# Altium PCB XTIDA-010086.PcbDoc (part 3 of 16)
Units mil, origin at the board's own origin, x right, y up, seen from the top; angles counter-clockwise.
Board outline 14763.78 x 8267.72 mil, 6 copper layers (Top Layer, GND Layer, Signal Layer 1, Signal Layer 2, Power Layer, Bottom Layer), stack 62 mil thick; 1933 components, 1002 nets, 4886 pads, 6482 vias.
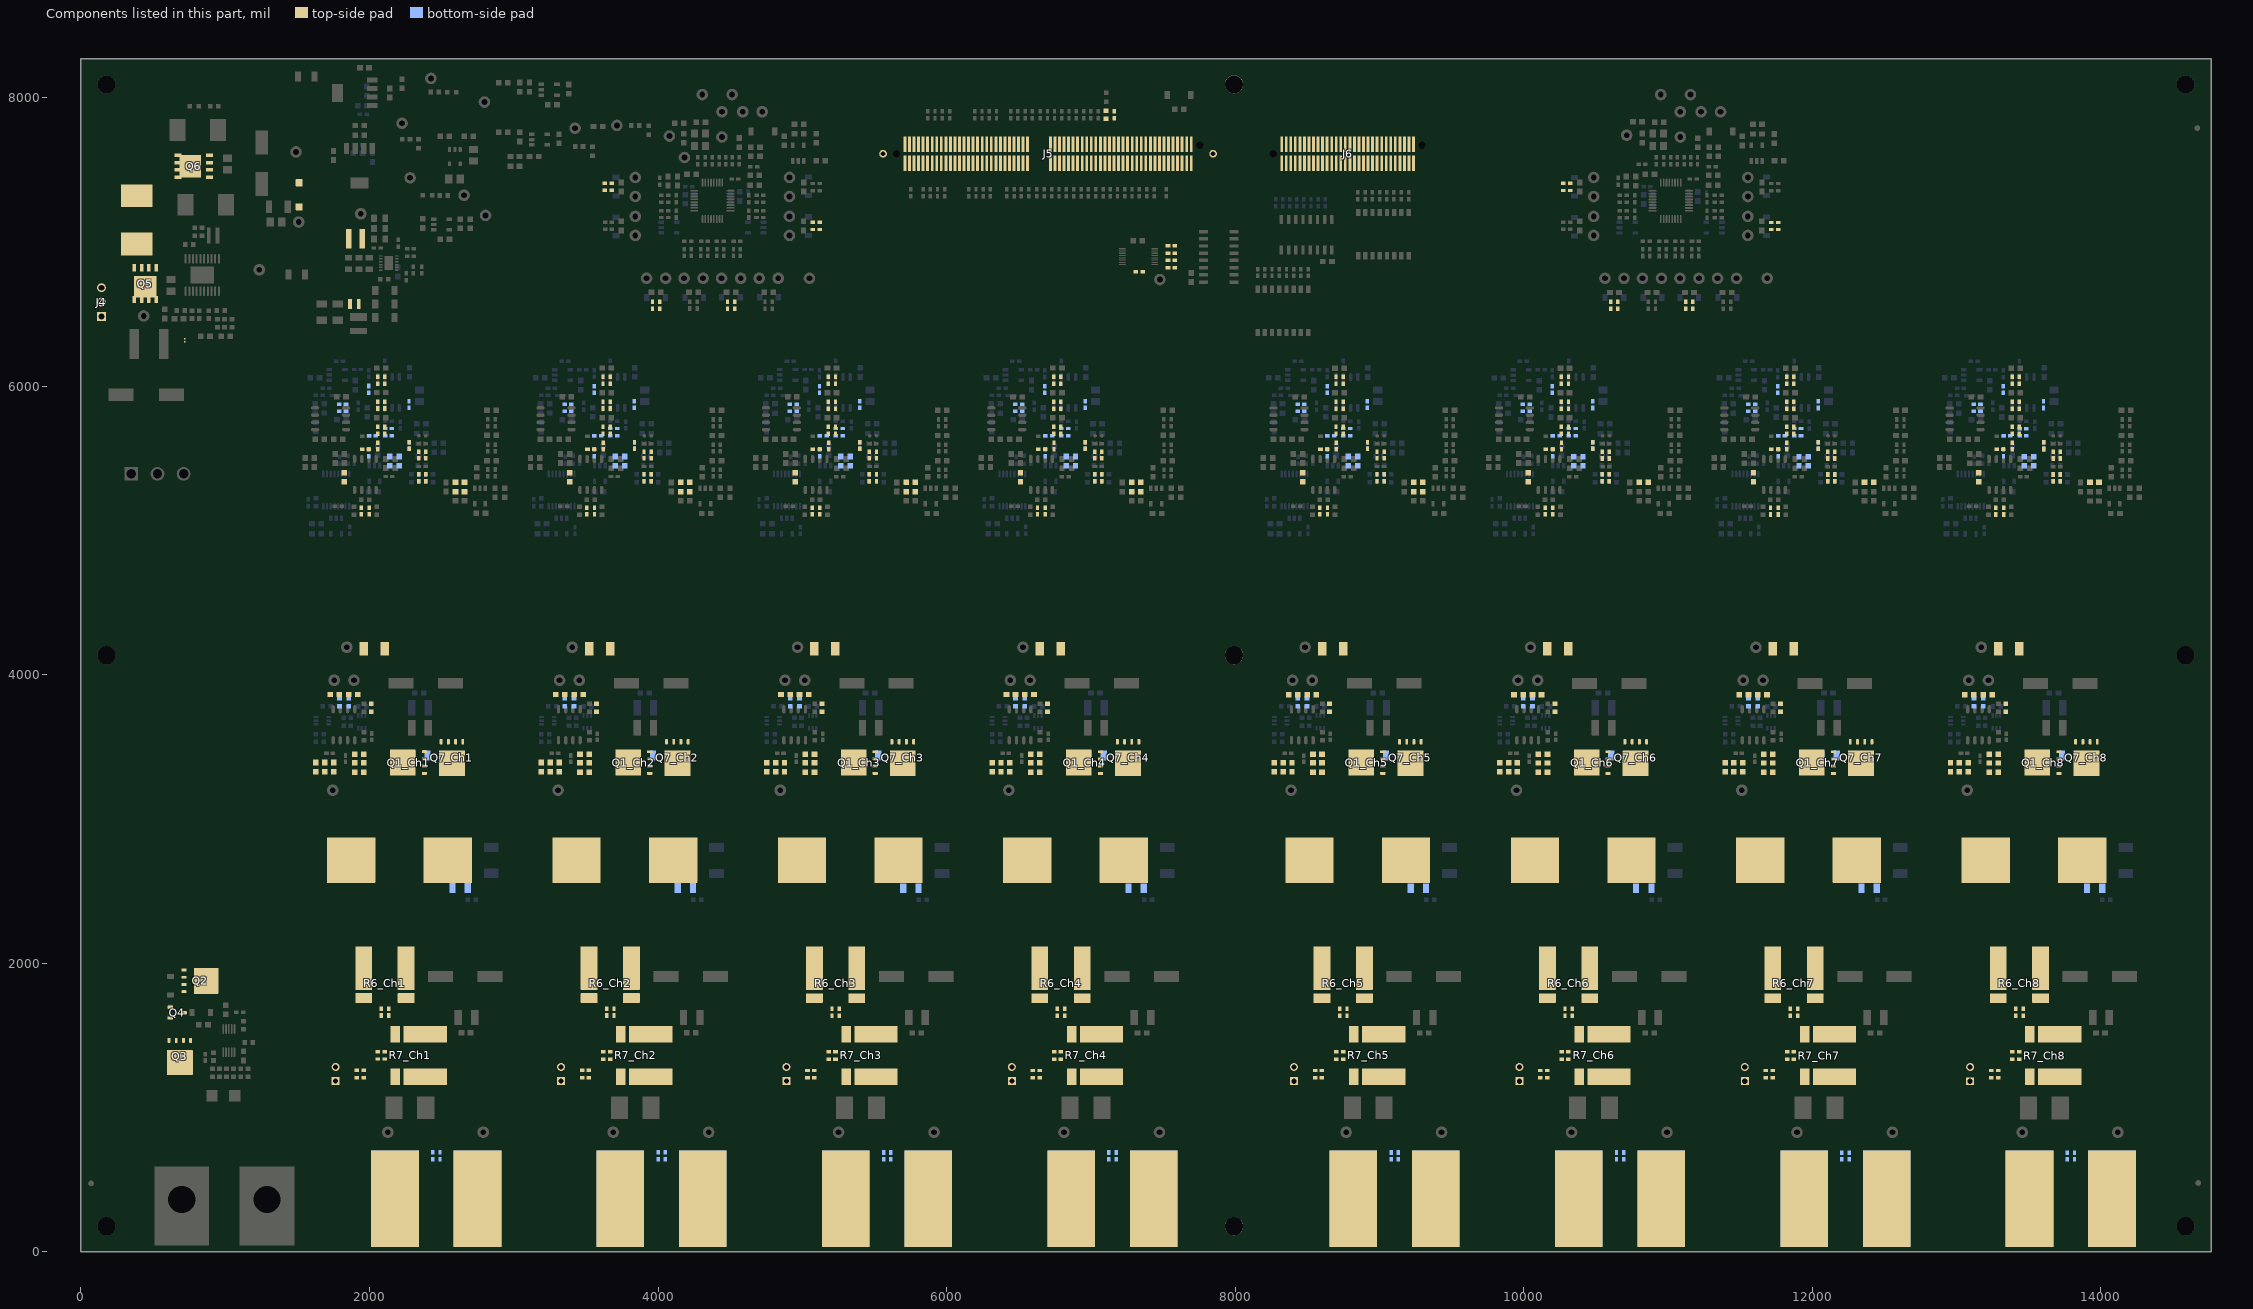
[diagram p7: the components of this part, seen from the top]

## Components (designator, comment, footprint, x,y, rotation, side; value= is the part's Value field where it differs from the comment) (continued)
H12 "2205" KEYSTONE_2205 177.17,4133.86 r180 bottom
H13 "NY PMS 440 0025 PH" "NY PMS 440 0025 PH"#1 7992.13,177.17 r0 top
H14 "NY PMS 440 0025 PH" "NY PMS 440 0025 PH"#1 7992.13,4133.86 r0 top
H15 "2205" KEYSTONE_2205 7992.13,177.17 r180 bottom
H16 "2205" KEYSTONE_2205 7992.13,4133.86 r180 bottom
H17 "NY PMS 440 0025 PH" "NY PMS 440 0025 PH"#1 7992.13,8090.55 r0 top
H18 "2205" KEYSTONE_2205 7992.13,8090.55 r180 bottom
J1_Ch1 "CB25-18-CY" FP-CB25-18-CY_CONN_TERM_LUG_25MM4_7MM9-MFG 2177,193 r90 top (schematic designator J1)
J1_Ch2 "CB25-18-CY" FP-CB25-18-CY_CONN_TERM_LUG_25MM4_7MM9-MFG 3739,192.92 r90 top (schematic designator J1)
J1_Ch3 "CB25-18-CY" FP-CB25-18-CY_CONN_TERM_LUG_25MM4_7MM9-MFG 5301,192.84 r90 top (schematic designator J1)
J1_Ch4 "CB25-18-CY" FP-CB25-18-CY_CONN_TERM_LUG_25MM4_7MM9-MFG 6863,192.76 r90 top (schematic designator J1)
J1_Ch5 "CB25-18-CY" FP-CB25-18-CY_CONN_TERM_LUG_25MM4_7MM9-MFG 8818.7,192.69 r90 top (schematic designator J1)
J1_Ch6 "CB25-18-CY" FP-CB25-18-CY_CONN_TERM_LUG_25MM4_7MM9-MFG 10380.7,192.61 r90 top (schematic designator J1)
J1_Ch7 "CB25-18-CY" FP-CB25-18-CY_CONN_TERM_LUG_25MM4_7MM9-MFG 11942.7,192.53 r90 top (schematic designator J1)
J1_Ch8 "CB25-18-CY" FP-CB25-18-CY_CONN_TERM_LUG_25MM4_7MM9-MFG 13504.7,192.45 r90 top (schematic designator J1)
J2_Ch1 "B2B-EH-A(LF)(SN)" JST_B2B-EH-A 1766,1232 r90 top (schematic designator J2)
J2_Ch2 "B2B-EH-A(LF)(SN)" JST_B2B-EH-A 3328,1231.92 r90 top (schematic designator J2)
J2_Ch3 "B2B-EH-A(LF)(SN)" JST_B2B-EH-A 4890,1231.84 r90 top (schematic designator J2)
J2_Ch4 "B2B-EH-A(LF)(SN)" JST_B2B-EH-A 6452,1231.76 r90 top (schematic designator J2)
J2_Ch5 "B2B-EH-A(LF)(SN)" JST_B2B-EH-A 8407.7,1231.69 r90 top (schematic designator J2)
J2_Ch6 "B2B-EH-A(LF)(SN)" JST_B2B-EH-A 9969.7,1231.61 r90 top (schematic designator J2)
J2_Ch7 "B2B-EH-A(LF)(SN)" JST_B2B-EH-A 11531.7,1231.53 r90 top (schematic designator J2)
J2_Ch8 "B2B-EH-A(LF)(SN)" JST_B2B-EH-A 13093.7,1231.45 r90 top (schematic designator J2)
J3_Ch1 "CB25-18-CY" FP-CB25-18-CY_CONN_TERM_LUG_25MM4_7MM9-MFG 2749,193 r90 top (schematic designator J3)
J3_Ch2 "CB25-18-CY" FP-CB25-18-CY_CONN_TERM_LUG_25MM4_7MM9-MFG 4311,192.92 r90 top (schematic designator J3)
J3_Ch3 "CB25-18-CY" FP-CB25-18-CY_CONN_TERM_LUG_25MM4_7MM9-MFG 5873,192.84 r90 top (schematic designator J3)
J3_Ch4 "CB25-18-CY" FP-CB25-18-CY_CONN_TERM_LUG_25MM4_7MM9-MFG 7435,192.76 r90 top (schematic designator J3)
J3_Ch5 "CB25-18-CY" FP-CB25-18-CY_CONN_TERM_LUG_25MM4_7MM9-MFG 9390.7,192.69 r90 top (schematic designator J3)
J3_Ch6 "CB25-18-CY" FP-CB25-18-CY_CONN_TERM_LUG_25MM4_7MM9-MFG 10952.7,192.61 r90 top (schematic designator J3)
J3_Ch7 "CB25-18-CY" FP-CB25-18-CY_CONN_TERM_LUG_25MM4_7MM9-MFG 12514.7,192.53 r90 top (schematic designator J3)
J3_Ch8 "CB25-18-CY" FP-CB25-18-CY_CONN_TERM_LUG_25MM4_7MM9-MFG 14076.7,192.45 r90 top (schematic designator J3)
J4 "0022284033" Molex_0022284033 143,6582 r90 top
J5 "HSEC8-160-01-L-DV-A-BL" controlCARD-120HSEC 6630.83,7608.76 r0 top
J6 "HSEC8-130-01-L-DV-A" controlCARD-180HSEC-60pinAddon 8778.98,7609.63 r0 top
L1_Ch1 "74437324010" WE-LHMI_4020 2033,4180 r0 top value=1uH (schematic designator L1)
L1_Ch2 "74437324010" WE-LHMI_4020 3595,4179.92 r0 top value=1uH (schematic designator L1)
L1_Ch3 "74437324010" WE-LHMI_4020 5157,4179.84 r0 top value=1uH (schematic designator L1)
L1_Ch4 "74437324010" WE-LHMI_4020 6719,4179.76 r0 top value=1uH (schematic designator L1)
L1_Ch5 "74437324010" WE-LHMI_4020 8674.7,4179.69 r0 top value=1uH (schematic designator L1)
L1_Ch6 "74437324010" WE-LHMI_4020 10236.7,4179.61 r0 top value=1uH (schematic designator L1)
L1_Ch7 "74437324010" WE-LHMI_4020 11798.7,4179.53 r0 top value=1uH (schematic designator L1)
L1_Ch8 "74437324010" WE-LHMI_4020 13360.7,4179.45 r0 top value=1uH (schematic designator L1)
L2_Ch1 "74437529203470" "WE-HCF ROUND_2920" 2208,2715 r180 top value=47uH (schematic designator L2)
L2_Ch2 "74437529203470" "WE-HCF ROUND_2920" 3770,2714.92 r180 top value=47uH (schematic designator L2)
L2_Ch3 "74437529203470" "WE-HCF ROUND_2920" 5332,2714.84 r180 top value=47uH (schematic designator L2)
L2_Ch4 "74437529203470" "WE-HCF ROUND_2920" 6894,2714.76 r180 top value=47uH (schematic designator L2)
L2_Ch5 "74437529203470" "WE-HCF ROUND_2920" 8849.7,2714.69 r180 top value=47uH (schematic designator L2)
L2_Ch6 "74437529203470" "WE-HCF ROUND_2920" 10411.7,2714.61 r180 top value=47uH (schematic designator L2)
L2_Ch7 "74437529203470" "WE-HCF ROUND_2920" 11973.7,2714.53 r180 top value=47uH (schematic designator L2)
L2_Ch8 "74437529203470" "WE-HCF ROUND_2920" 13535.7,2714.45 r180 top value=47uH (schematic designator L2)
L3 "MSS1278-473MLB" mss1278 387.5,7151.7 r90 top value=47uH
L4 "BLM41PG102SN1L" 1806_HighSpeed 1513,7325.54 r270 top value="1000 ohm"
L5 "MAKK2016T4R7M" MAKK2016 1896.5,6569.48 r0 top value=4.7uH
L6 "XFL4020-472MEB" XFL4020 1903,7020 r0 top value=4.7uH
LBL1 "THT-14-423-10" Label_650x200 14581.65,7250.63 r90 top
Logo1 "CE Mark" CE_Mark_5mm 13079.56,7298.51 r0 top
Logo3 "FCC disclaimer" FCC_disclaimer 15397.74,615.15 r90 top
Logo4 "WEEE logo" WEEE_Minimum 12658,7372 r0 top
LOGO5 "CAUTION HOT SURFACE" IEC_HotSurface_Small 13911,7299.76 r0 top
Logo6 "Pb-Free Symbol" Pb-Free_Overlay_Small 14196.15,7320.26 r0 top
Logo7 "ESD Susceptible" ESD_Overlay_Medium 13495,7311.26 r0 top
NT1 "Net-Tie" Net-Tie_10mil 721,6316.7 r270 top net-tie
Q1_Ch1 "CSD18504Q5A" DQJ0008A 2270.96,3391 r180 top value=40V (schematic designator Q1)
Q1_Ch2 "CSD18504Q5A" DQJ0008A 3832.96,3390.92 r180 top value=40V (schematic designator Q1)
Q1_Ch3 "CSD18504Q5A" DQJ0008A 5394.96,3390.84 r180 top value=40V (schematic designator Q1)
Q1_Ch4 "CSD18504Q5A" DQJ0008A 6956.96,3390.76 r180 top value=40V (schematic designator Q1)
Q1_Ch5 "CSD18504Q5A" DQJ0008A 8912.66,3390.69 r180 top value=40V (schematic designator Q1)
Q1_Ch6 "CSD18504Q5A" DQJ0008A 10474.66,3390.61 r180 top value=40V (schematic designator Q1)
Q1_Ch7 "CSD18504Q5A" DQJ0008A 12036.66,3390.53 r180 top value=40V (schematic designator Q1)
Q1_Ch8 "CSD18504Q5A" DQJ0008A 13598.66,3390.45 r180 top value=40V (schematic designator Q1)
Q2 "CSD16570Q5B" DNK0008A 825.94,1878 r0 top value=25V
Q3 "CSD16570Q5B" DNK0008A 686.33,1354.54 r270 top value=25V
Q4 "MMBTA06-7-F" SOT-23 667.33,1657.56 r0 top value="80 V"
Q5 "SI7454DDP-T1-GE3" PowerPAK_SO-8 446.5,6710.7 r270 top value=100V
Q6 "SI7454DDP-T1-GE3" PowerPAK_SO-8 781.5,7523.7 r180 top value=100V
Q7_Ch1 "CSD18504Q5A" DQJ0008A 2572,3425.04 r270 top value=40V (schematic designator Q7)
Q7_Ch2 "CSD18504Q5A" DQJ0008A 4134,3424.96 r270 top value=40V (schematic designator Q7)
Q7_Ch3 "CSD18504Q5A" DQJ0008A 5696,3424.88 r270 top value=40V (schematic designator Q7)
Q7_Ch4 "CSD18504Q5A" DQJ0008A 7258,3424.8 r270 top value=40V (schematic designator Q7)
Q7_Ch5 "CSD18504Q5A" DQJ0008A 9213.7,3424.72 r270 top value=40V (schematic designator Q7)
Q7_Ch6 "CSD18504Q5A" DQJ0008A 10775.7,3424.65 r270 top value=40V (schematic designator Q7)
Q7_Ch7 "CSD18504Q5A" DQJ0008A 12337.7,3424.57 r270 top value=40V (schematic designator Q7)
Q7_Ch8 "CSD18504Q5A" DQJ0008A 13899.7,3424.49 r270 top value=40V (schematic designator Q7)
R1_Ch1 "RC0603FR-0710KL" 0603 1888.11,3862.31 r0 top value=10.0k (schematic designator R1)
R1_Ch2 "RC0603FR-0710KL" 0603 3450.11,3862.24 r0 top value=10.0k (schematic designator R1)
R1_Ch3 "RC0603FR-0710KL" 0603 5012.11,3862.16 r0 top value=10.0k (schematic designator R1)
R1_Ch4 "RC0603FR-0710KL" 0603 6574.11,3862.08 r0 top value=10.0k (schematic designator R1)
R1_Ch5 "RC0603FR-0710KL" 0603 8529.81,3862 r0 top value=10.0k (schematic designator R1)
R1_Ch6 "RC0603FR-0710KL" 0603 10091.81,3861.92 r0 top value=10.0k (schematic designator R1)
R1_Ch7 "RC0603FR-0710KL" 0603 11653.81,3861.84 r0 top value=10.0k (schematic designator R1)
R1_Ch8 "RC0603FR-0710KL" 0603 13215.81,3861.76 r0 top value=10.0k (schematic designator R1)
R2_Ch1 "RC0603JR-070RL" 0603L 1856.11,3808.11 r270 bottom value=0 (schematic designator R2)
R2_Ch2 "RC0603JR-070RL" 0603L 3418.11,3808.04 r270 bottom value=0 (schematic designator R2)
R2_Ch3 "RC0603JR-070RL" 0603L 4980.11,3807.96 r270 bottom value=0 (schematic designator R2)
R2_Ch4 "RC0603JR-070RL" 0603L 6542.11,3807.88 r270 bottom value=0 (schematic designator R2)
R2_Ch5 "RC0603JR-070RL" 0603L 8497.81,3807.8 r270 bottom value=0 (schematic designator R2)
R2_Ch6 "RC0603JR-070RL" 0603L 10059.81,3807.72 r270 bottom value=0 (schematic designator R2)
R2_Ch7 "RC0603JR-070RL" 0603L 11621.81,3807.64 r270 bottom value=0 (schematic designator R2)
R2_Ch8 "RC0603JR-070RL" 0603L 13183.81,3807.56 r270 bottom value=0 (schematic designator R2)
R3_Ch1 "RC0603JR-070RL" 0603L 1792.11,3808.11 r270 bottom value=0 (schematic designator R3)
R3_Ch2 "RC0603JR-070RL" 0603L 3354.11,3808.04 r270 bottom value=0 (schematic designator R3)
R3_Ch3 "RC0603JR-070RL" 0603L 4916.11,3807.96 r270 bottom value=0 (schematic designator R3)
R3_Ch4 "RC0603JR-070RL" 0603L 6478.11,3807.88 r270 bottom value=0 (schematic designator R3)
R3_Ch5 "RC0603JR-070RL" 0603L 8433.81,3807.8 r270 bottom value=0 (schematic designator R3)
R3_Ch6 "RC0603JR-070RL" 0603L 9995.81,3807.72 r270 bottom value=0 (schematic designator R3)
R3_Ch7 "RC0603JR-070RL" 0603L 11557.81,3807.64 r270 bottom value=0 (schematic designator R3)
R3_Ch8 "RC0603JR-070RL" 0603L 13119.81,3807.56 r270 bottom value=0 (schematic designator R3)
R4_Ch1 "RC1206FR-0710RL" 1206L 2350,3441 r0 bottom value=10.0 (schematic designator R4)
R4_Ch2 "RC1206FR-0710RL" 1206L 3912,3440.92 r0 bottom value=10.0 (schematic designator R4)
R4_Ch3 "RC1206FR-0710RL" 1206L 5474,3440.84 r0 bottom value=10.0 (schematic designator R4)
R4_Ch4 "RC1206FR-0710RL" 1206L 7036,3440.76 r0 bottom value=10.0 (schematic designator R4)
R4_Ch5 "RC1206FR-0710RL" 1206L 8991.7,3440.69 r0 bottom value=10.0 (schematic designator R4)
R4_Ch6 "RC1206FR-0710RL" 1206L 10553.7,3440.61 r0 bottom value=10.0 (schematic designator R4)
R4_Ch7 "RC1206FR-0710RL" 1206L 12115.7,3440.53 r0 bottom value=10.0 (schematic designator R4)
R4_Ch8 "RC1206FR-0710RL" 1206L 13677.7,3440.45 r0 bottom value=10.0 (schematic designator R4)
R5_Ch1 "RC0603FR-0710KL" 0603 1760.11,3862.31 r0 top value=10.0k (schematic designator R5)
R5_Ch2 "RC0603FR-0710KL" 0603 3322.11,3862.24 r0 top value=10.0k (schematic designator R5)
R5_Ch3 "RC0603FR-0710KL" 0603 4884.11,3862.16 r0 top value=10.0k (schematic designator R5)
R5_Ch4 "RC0603FR-0710KL" 0603 6446.11,3862.08 r0 top value=10.0k (schematic designator R5)
R5_Ch5 "RC0603FR-0710KL" 0603 8401.81,3862 r0 top value=10.0k (schematic designator R5)
R5_Ch6 "RC0603FR-0710KL" 0603 9963.81,3861.92 r0 top value=10.0k (schematic designator R5)
R5_Ch7 "RC0603FR-0710KL" 0603 11525.81,3861.84 r0 top value=10.0k (schematic designator R5)
R5_Ch8 "RC0603FR-0710KL" 0603 13087.81,3861.76 r0 top value=10.0k (schematic designator R5)
R6_Ch1 "Y14880R00500B9R" CSM3637Z 2107,1921 r270 top value=5mOhm (schematic designator R6)
R6_Ch2 "Y14880R00500B9R" CSM3637Z 3669,1920.92 r270 top value=5mOhm (schematic designator R6)
R6_Ch3 "Y14880R00500B9R" CSM3637Z 5231,1920.84 r270 top value=5mOhm (schematic designator R6)
R6_Ch4 "Y14880R00500B9R" CSM3637Z 6793,1920.76 r270 top value=5mOhm (schematic designator R6)
R6_Ch5 "Y14880R00500B9R" CSM3637Z 8748.7,1920.69 r270 top value=5mOhm (schematic designator R6)
R6_Ch6 "Y14880R00500B9R" CSM3637Z 10310.7,1920.61 r270 top value=5mOhm (schematic designator R6)
R6_Ch7 "Y14880R00500B9R" CSM3637Z 11872.7,1920.53 r270 top value=5mOhm (schematic designator R6)
R6_Ch8 "Y14880R00500B9R" CSM3637Z 13434.7,1920.45 r270 top value=5mOhm (schematic designator R6)
R7_Ch1 "Y14880R00500B9R" CSM3637Z 2342,1361 r180 top value=5mOhm (schematic designator R7)
R7_Ch2 "Y14880R00500B9R" CSM3637Z 3904,1360.92 r180 top value=5mOhm (schematic designator R7)
R7_Ch3 "Y14880R00500B9R" CSM3637Z 5466,1360.84 r180 top value=5mOhm (schematic designator R7)
R7_Ch4 "Y14880R00500B9R" CSM3637Z 7028,1360.76 r180 top value=5mOhm (schematic designator R7)
R7_Ch5 "Y14880R00500B9R" CSM3637Z 8983.7,1360.69 r180 top value=5mOhm (schematic designator R7)
R7_Ch6 "Y14880R00500B9R" CSM3637Z 10545.7,1360.61 r180 top value=5mOhm (schematic designator R7)
R7_Ch7 "Y14880R00500B9R" CSM3637Z 12107.7,1360.53 r180 top value=5mOhm (schematic designator R7)
R7_Ch8 "Y14880R00500B9R" CSM3637Z 13669.7,1360.45 r180 top value=5mOhm (schematic designator R7)
R8_Ch1 "RC0603JR-070RL" 0603L 2012.39,3771.26 r90 top value=0 (schematic designator R8)
R8_Ch2 "RC0603JR-070RL" 0603L 3574.39,3771.18 r90 top value=0 (schematic designator R8)
R8_Ch3 "RC0603JR-070RL" 0603L 5136.39,3771.1 r90 top value=0 (schematic designator R8)
R8_Ch4 "RC0603JR-070RL" 0603L 6698.39,3771.02 r90 top value=0 (schematic designator R8)
R8_Ch5 "RC0603JR-070RL" 0603L 8654.09,3770.94 r90 top value=0 (schematic designator R8)
R8_Ch6 "RC0603JR-070RL" 0603L 10216.09,3770.86 r90 top value=0 (schematic designator R8)
R8_Ch7 "RC0603JR-070RL" 0603L 11778.09,3770.79 r90 top value=0 (schematic designator R8)
R8_Ch8 "RC0603JR-070RL" 0603L 13340.09,3770.71 r90 top value=0 (schematic designator R8)
R9_Ch1 "RC1206FR-0710RL" 1206L 2628,2520 r0 bottom value=10.0 (schematic designator R9)
R9_Ch2 "RC1206FR-0710RL" 1206L 4190,2519.92 r0 bottom value=10.0 (schematic designator R9)
R9_Ch3 "RC1206FR-0710RL" 1206L 5752,2519.84 r0 bottom value=10.0 (schematic designator R9)
R9_Ch4 "RC1206FR-0710RL" 1206L 7314,2519.76 r0 bottom value=10.0 (schematic designator R9)
R9_Ch5 "RC1206FR-0710RL" 1206L 9269.7,2519.69 r0 bottom value=10.0 (schematic designator R9)
R9_Ch6 "RC1206FR-0710RL" 1206L 10831.7,2519.61 r0 bottom value=10.0 (schematic designator R9)
R9_Ch7 "RC1206FR-0710RL" 1206L 12393.7,2519.53 r0 bottom value=10.0 (schematic designator R9)
R9_Ch8 "RC1206FR-0710RL" 1206L 13955.7,2519.45 r0 bottom value=10.0 (schematic designator R9)
R10_Ch1 "CRCW04020000Z0ED" 0402 2439,665 r270 bottom value=0 (schematic designator R10)
R10_Ch2 "CRCW04020000Z0ED" 0402 4001,664.92 r270 bottom value=0 (schematic designator R10)
R10_Ch3 "CRCW04020000Z0ED" 0402 5563,664.84 r270 bottom value=0 (schematic designator R10)
R10_Ch4 "CRCW04020000Z0ED" 0402 7125,664.76 r270 bottom value=0 (schematic designator R10)
R10_Ch5 "CRCW04020000Z0ED" 0402 9080.7,664.69 r270 bottom value=0 (schematic designator R10)
R10_Ch6 "CRCW04020000Z0ED" 0402 10642.7,664.61 r270 bottom value=0 (schematic designator R10)
R10_Ch7 "CRCW04020000Z0ED" 0402 12204.7,664.53 r270 bottom value=0 (schematic designator R10)
R10_Ch8 "CRCW04020000Z0ED" 0402 13766.7,664.45 r270 bottom value=0 (schematic designator R10)
R11_Ch1 "CRCW06032R00FKEA" 0603 1928.87,3449.29 r180 top value=2.00 (schematic designator R11)
R11_Ch2 "CRCW06032R00FKEA" 0603 3490.87,3449.21 r180 top value=2.00 (schematic designator R11)
R11_Ch3 "CRCW06032R00FKEA" 0603 5052.87,3449.13 r180 top value=2.00 (schematic designator R11)
R11_Ch4 "CRCW06032R00FKEA" 0603 6614.87,3449.05 r180 top value=2.00 (schematic designator R11)
R11_Ch5 "CRCW06032R00FKEA" 0603 8570.57,3448.97 r180 top value=2.00 (schematic designator R11)
R11_Ch6 "CRCW06032R00FKEA" 0603 10132.57,3448.9 r180 top value=2.00 (schematic designator R11)
R11_Ch7 "CRCW06032R00FKEA" 0603 11694.57,3448.82 r180 top value=2.00 (schematic designator R11)
R11_Ch8 "CRCW06032R00FKEA" 0603 13256.57,3448.74 r180 top value=2.00 (schematic designator R11)
R12_Ch1 "CRCW04020000Z0ED" 0402 2082,1661.34 r90 top value=0 (schematic designator R12)
R12_Ch2 "CRCW04020000Z0ED" 0402 3644,1661.26 r90 top value=0 (schematic designator R12)
R12_Ch3 "CRCW04020000Z0ED" 0402 5206,1661.18 r90 top value=0 (schematic designator R12)
R12_Ch4 "CRCW04020000Z0ED" 0402 6768,1661.1 r90 top value=0 (schematic designator R12)
R12_Ch5 "CRCW04020000Z0ED" 0402 8723.7,1661.02 r90 top value=0 (schematic designator R12)
R12_Ch6 "CRCW04020000Z0ED" 0402 10285.7,1660.95 r90 top value=0 (schematic designator R12)
R12_Ch7 "CRCW04020000Z0ED" 0402 11847.7,1660.87 r90 top value=0 (schematic designator R12)
R12_Ch8 "CRCW04020000Z0ED" 0402 13409.7,1660.79 r90 top value=0 (schematic designator R12)
R13_Ch1 "CRCW04020000Z0ED" 0402 2133,1661.34 r90 top value=0 (schematic designator R13)
R13_Ch2 "CRCW04020000Z0ED" 0402 3695,1661.26 r90 top value=0 (schematic designator R13)
R13_Ch3 "CRCW04020000Z0ED" 0402 5257,1661.18 r90 top value=0 (schematic designator R13)
R13_Ch4 "CRCW04020000Z0ED" 0402 6819,1661.1 r90 top value=0 (schematic designator R13)
R13_Ch5 "CRCW04020000Z0ED" 0402 8774.7,1661.02 r90 top value=0 (schematic designator R13)
R13_Ch6 "CRCW04020000Z0ED" 0402 10336.7,1660.95 r90 top value=0 (schematic designator R13)
R13_Ch7 "CRCW04020000Z0ED" 0402 11898.7,1660.87 r90 top value=0 (schematic designator R13)
R13_Ch8 "CRCW04020000Z0ED" 0402 13460.7,1660.79 r90 top value=0 (schematic designator R13)
R14_Ch1 "CRCW04020000Z0ED" 0402 1935.63,1207 r180 top value=0 (schematic designator R14)
R14_Ch2 "CRCW04020000Z0ED" 0402 3497.63,1206.92 r180 top value=0 (schematic designator R14)
R14_Ch3 "CRCW04020000Z0ED" 0402 5059.63,1206.84 r180 top value=0 (schematic designator R14)
R14_Ch4 "CRCW04020000Z0ED" 0402 6621.63,1206.76 r180 top value=0 (schematic designator R14)
R14_Ch5 "CRCW04020000Z0ED" 0402 8577.33,1206.69 r180 top value=0 (schematic designator R14)
R14_Ch6 "CRCW04020000Z0ED" 0402 10139.33,1206.61 r180 top value=0 (schematic designator R14)
R14_Ch7 "CRCW04020000Z0ED" 0402 11701.33,1206.53 r180 top value=0 (schematic designator R14)
R14_Ch8 "CRCW04020000Z0ED" 0402 13263.33,1206.45 r180 top value=0 (schematic designator R14)
R15_Ch1 "CRCW04020000Z0ED" 0402 2082.34,1386 r0 top value=0 (schematic designator R15)
R15_Ch2 "CRCW04020000Z0ED" 0402 3644.34,1385.92 r0 top value=0 (schematic designator R15)
R15_Ch3 "CRCW04020000Z0ED" 0402 5206.34,1385.84 r0 top value=0 (schematic designator R15)
R15_Ch4 "CRCW04020000Z0ED" 0402 6768.34,1385.76 r0 top value=0 (schematic designator R15)
R15_Ch5 "CRCW04020000Z0ED" 0402 8724.04,1385.69 r0 top value=0 (schematic designator R15)
R15_Ch6 "CRCW04020000Z0ED" 0402 10286.04,1385.61 r0 top value=0 (schematic designator R15)
R15_Ch7 "CRCW04020000Z0ED" 0402 11848.04,1385.53 r0 top value=0 (schematic designator R15)
R15_Ch8 "CRCW04020000Z0ED" 0402 13410.04,1385.45 r0 top value=0 (schematic designator R15)
R16_Ch1 "CRCW04020000Z0ED" 0402 2082.34,1336 r0 top value=0 (schematic designator R16)
R16_Ch2 "CRCW04020000Z0ED" 0402 3644.34,1335.92 r0 top value=0 (schematic designator R16)
R16_Ch3 "CRCW04020000Z0ED" 0402 5206.34,1335.84 r0 top value=0 (schematic designator R16)
R16_Ch4 "CRCW04020000Z0ED" 0402 6768.34,1335.76 r0 top value=0 (schematic designator R16)
R16_Ch5 "CRCW04020000Z0ED" 0402 8724.04,1335.69 r0 top value=0 (schematic designator R16)
R16_Ch6 "CRCW04020000Z0ED" 0402 10286.04,1335.61 r0 top value=0 (schematic designator R16)
R16_Ch7 "CRCW04020000Z0ED" 0402 11848.04,1335.53 r0 top value=0 (schematic designator R16)
R16_Ch8 "CRCW04020000Z0ED" 0402 13410.04,1335.45 r0 top value=0 (schematic designator R16)
R17_Ch1 "CRCW04020000Z0ED" 0402 1935.63,1257 r180 top value=0 (schematic designator R17)
R17_Ch2 "CRCW04020000Z0ED" 0402 3497.63,1256.92 r180 top value=0 (schematic designator R17)
R17_Ch3 "CRCW04020000Z0ED" 0402 5059.63,1256.84 r180 top value=0 (schematic designator R17)
R17_Ch4 "CRCW04020000Z0ED" 0402 6621.63,1256.76 r180 top value=0 (schematic designator R17)
R17_Ch5 "CRCW04020000Z0ED" 0402 8577.33,1256.69 r180 top value=0 (schematic designator R17)
R17_Ch6 "CRCW04020000Z0ED" 0402 10139.33,1256.61 r180 top value=0 (schematic designator R17)
R17_Ch7 "CRCW04020000Z0ED" 0402 11701.33,1256.53 r180 top value=0 (schematic designator R17)
R17_Ch8 "CRCW04020000Z0ED" 0402 13263.33,1256.45 r180 top value=0 (schematic designator R17)
R18_Ch1 "RC0603FR-0710KL" 0603 1928.87,3323.07 r0 top value=10.0k (schematic designator R18)
R18_Ch2 "RC0603FR-0710KL" 0603 3490.87,3322.99 r0 top value=10.0k (schematic designator R18)
R18_Ch3 "RC0603FR-0710KL" 0603 5052.87,3322.91 r0 top value=10.0k (schematic designator R18)
R18_Ch4 "RC0603FR-0710KL" 0603 6614.87,3322.83 r0 top value=10.0k (schematic designator R18)
R18_Ch5 "RC0603FR-0710KL" 0603 8570.57,3322.75 r0 top value=10.0k (schematic designator R18)
R18_Ch6 "RC0603FR-0710KL" 0603 10132.57,3322.68 r0 top value=10.0k (schematic designator R18)
R18_Ch7 "RC0603FR-0710KL" 0603 11694.57,3322.6 r0 top value=10.0k (schematic designator R18)
R18_Ch8 "RC0603FR-0710KL" 0603 13256.57,3322.52 r0 top value=10.0k (schematic designator R18)
R19_Ch1 "RC0603FR-071RL" 0603 1928.87,3388.42 r0 top value=1.00 (schematic designator R19)
R19_Ch2 "RC0603FR-071RL" 0603 3490.87,3388.34 r0 top value=1.00 (schematic designator R19)
R19_Ch3 "RC0603FR-071RL" 0603 5052.87,3388.26 r0 top value=1.00 (schematic designator R19)
R19_Ch4 "RC0603FR-071RL" 0603 6614.87,3388.18 r0 top value=1.00 (schematic designator R19)
R19_Ch5 "RC0603FR-071RL" 0603 8570.57,3388.1 r0 top value=1.00 (schematic designator R19)
R19_Ch6 "RC0603FR-071RL" 0603 10132.57,3388.02 r0 top value=1.00 (schematic designator R19)
R19_Ch7 "RC0603FR-071RL" 0603 11694.57,3387.94 r0 top value=1.00 (schematic designator R19)
R19_Ch8 "RC0603FR-071RL" 0603 13256.57,3387.86 r0 top value=1.00 (schematic designator R19)
R20_Ch1 "CRCW04020000Z0ED" 0402 2489,665 r90 bottom value=0 (schematic designator R20)
R20_Ch2 "CRCW04020000Z0ED" 0402 4051,664.92 r90 bottom value=0 (schematic designator R20)
R20_Ch3 "CRCW04020000Z0ED" 0402 5613,664.84 r90 bottom value=0 (schematic designator R20)
R20_Ch4 "CRCW04020000Z0ED" 0402 7175,664.76 r90 bottom value=0 (schematic designator R20)
R20_Ch5 "CRCW04020000Z0ED" 0402 9130.7,664.69 r90 bottom value=0 (schematic designator R20)
R20_Ch6 "CRCW04020000Z0ED" 0402 10692.7,664.61 r90 bottom value=0 (schematic designator R20)
R20_Ch7 "CRCW04020000Z0ED" 0402 12254.7,664.53 r90 bottom value=0 (schematic designator R20)
R20_Ch8 "CRCW04020000Z0ED" 0402 13816.7,664.45 r90 bottom value=0 (schematic designator R20)
R21_Ch1 "CRCW06032R00FKEA" 0603 1752.36,3359.09 r90 top value=2.00 (schematic designator R21)
R21_Ch2 "CRCW06032R00FKEA" 0603 3314.36,3359.01 r90 top value=2.00 (schematic designator R21)
R21_Ch3 "CRCW06032R00FKEA" 0603 4876.36,3358.93 r90 top value=2.00 (schematic designator R21)
R21_Ch4 "CRCW06032R00FKEA" 0603 6438.36,3358.86 r90 top value=2.00 (schematic designator R21)
R21_Ch5 "CRCW06032R00FKEA" 0603 8394.06,3358.78 r90 top value=2.00 (schematic designator R21)
R21_Ch6 "CRCW06032R00FKEA" 0603 9956.06,3358.7 r90 top value=2.00 (schematic designator R21)
R21_Ch7 "CRCW06032R00FKEA" 0603 11518.06,3358.62 r90 top value=2.00 (schematic designator R21)
R21_Ch8 "CRCW06032R00FKEA" 0603 13080.06,3358.54 r90 top value=2.00 (schematic designator R21)
R22_Ch1 "CRCW040210K0FKED" 0402 2390,5364.05 r90 top value=10.0k (schematic designator R22)
R22_Ch2 "CRCW040210K0FKED" 0402 3952,5363.97 r90 top value=10.0k (schematic designator R22)
R22_Ch3 "CRCW040210K0FKED" 0402 5514,5363.89 r90 top value=10.0k (schematic designator R22)
R22_Ch4 "CRCW040210K0FKED" 0402 7076,5363.81 r90 top value=10.0k (schematic designator R22)
R22_Ch5 "CRCW040210K0FKED" 0402 9031.7,5363.73 r90 top value=10.0k (schematic designator R22)
R22_Ch6 "CRCW040210K0FKED" 0402 10593.7,5363.65 r90 top value=10.0k (schematic designator R22)
R22_Ch7 "CRCW040210K0FKED" 0402 12155.7,5363.57 r90 top value=10.0k (schematic designator R22)
R22_Ch8 "CRCW040210K0FKED" 0402 13717.7,5363.5 r90 top value=10.0k (schematic designator R22)
R23_Ch1 "CRCW040210K0FKED" 0402 2390,5522.05 r90 top value=10.0k (schematic designator R23)
R23_Ch2 "CRCW040210K0FKED" 0402 3952,5521.97 r90 top value=10.0k (schematic designator R23)
R23_Ch3 "CRCW040210K0FKED" 0402 5514,5521.89 r90 top value=10.0k (schematic designator R23)
R23_Ch4 "CRCW040210K0FKED" 0402 7076,5521.81 r90 top value=10.0k (schematic designator R23)
R23_Ch5 "CRCW040210K0FKED" 0402 9031.7,5521.73 r90 top value=10.0k (schematic designator R23)
R23_Ch6 "CRCW040210K0FKED" 0402 10593.7,5521.65 r90 top value=10.0k (schematic designator R23)
R23_Ch7 "CRCW040210K0FKED" 0402 12155.7,5521.57 r90 top value=10.0k (schematic designator R23)
R23_Ch8 "CRCW040210K0FKED" 0402 13717.7,5521.5 r90 top value=10.0k (schematic designator R23)
R24_Ch1 "RC0603FR-0710KL" 0603 1629.36,3359.09 r270 top value=10.0k (schematic designator R24)
R24_Ch2 "RC0603FR-0710KL" 0603 3191.36,3359.01 r270 top value=10.0k (schematic designator R24)
R24_Ch3 "RC0603FR-0710KL" 0603 4753.36,3358.93 r270 top value=10.0k (schematic designator R24)
R24_Ch4 "RC0603FR-0710KL" 0603 6315.36,3358.86 r270 top value=10.0k (schematic designator R24)
R24_Ch5 "RC0603FR-0710KL" 0603 8271.06,3358.78 r270 top value=10.0k (schematic designator R24)
R24_Ch6 "RC0603FR-0710KL" 0603 9833.06,3358.7 r270 top value=10.0k (schematic designator R24)
R24_Ch7 "RC0603FR-0710KL" 0603 11395.06,3358.62 r270 top value=10.0k (schematic designator R24)
R24_Ch8 "RC0603FR-0710KL" 0603 12957.06,3358.54 r270 top value=10.0k (schematic designator R24)
R25_Ch1 "RC0603FR-071RL" 0603 1690.83,3359.09 r270 top value=1.00 (schematic designator R25)
R25_Ch2 "RC0603FR-071RL" 0603 3252.83,3359.01 r270 top value=1.00 (schematic designator R25)
R25_Ch3 "RC0603FR-071RL" 0603 4814.83,3358.93 r270 top value=1.00 (schematic designator R25)
R25_Ch4 "RC0603FR-071RL" 0603 6376.83,3358.86 r270 top value=1.00 (schematic designator R25)
R25_Ch5 "RC0603FR-071RL" 0603 8332.53,3358.78 r270 top value=1.00 (schematic designator R25)
R25_Ch6 "RC0603FR-071RL" 0603 9894.53,3358.7 r270 top value=1.00 (schematic designator R25)
R25_Ch7 "RC0603FR-071RL" 0603 11456.53,3358.62 r270 top value=1.00 (schematic designator R25)
R25_Ch8 "RC0603FR-071RL" 0603 13018.53,3358.54 r270 top value=1.00 (schematic designator R25)
R26_Ch1 "CRCW040210K0FKED" 0402 2341,5364.05 r90 top value=10.0k (schematic designator R26)
R26_Ch2 "CRCW040210K0FKED" 0402 3903,5363.97 r90 top value=10.0k (schematic designator R26)
R26_Ch3 "CRCW040210K0FKED" 0402 5465,5363.89 r90 top value=10.0k (schematic designator R26)
R26_Ch4 "CRCW040210K0FKED" 0402 7027,5363.81 r90 top value=10.0k (schematic designator R26)
R26_Ch5 "CRCW040210K0FKED" 0402 8982.7,5363.73 r90 top value=10.0k (schematic designator R26)
R26_Ch6 "CRCW040210K0FKED" 0402 10544.7,5363.65 r90 top value=10.0k (schematic designator R26)
R26_Ch7 "CRCW040210K0FKED" 0402 12106.7,5363.57 r90 top value=10.0k (schematic designator R26)
R26_Ch8 "CRCW040210K0FKED" 0402 13668.7,5363.5 r90 top value=10.0k (schematic designator R26)
R27_Ch1 "CRCW040210K0FKED" 0402 2341,5522.05 r90 top value=10.0k (schematic designator R27)
R27_Ch2 "CRCW040210K0FKED" 0402 3903,5521.97 r90 top value=10.0k (schematic designator R27)
R27_Ch3 "CRCW040210K0FKED" 0402 5465,5521.89 r90 top value=10.0k (schematic designator R27)
R27_Ch4 "CRCW040210K0FKED" 0402 7027,5521.81 r90 top value=10.0k (schematic designator R27)
R27_Ch5 "CRCW040210K0FKED" 0402 8982.7,5521.73 r90 top value=10.0k (schematic designator R27)
R27_Ch6 "CRCW040210K0FKED" 0402 10544.7,5521.65 r90 top value=10.0k (schematic designator R27)
R27_Ch7 "CRCW040210K0FKED" 0402 12106.7,5521.57 r90 top value=10.0k (schematic designator R27)
R27_Ch8 "CRCW040210K0FKED" 0402 13668.7,5521.5 r90 top value=10.0k (schematic designator R27)
R28_Ch1 "CRCW04020000Z0ED" 0402 1944,5134.05 r90 top value=0 (schematic designator R28)
R28_Ch2 "CRCW04020000Z0ED" 0402 3506,5133.97 r90 top value=0 (schematic designator R28)
R28_Ch3 "CRCW04020000Z0ED" 0402 5068,5133.89 r90 top value=0 (schematic designator R28)
R28_Ch4 "CRCW04020000Z0ED" 0402 6630,5133.81 r90 top value=0 (schematic designator R28)
R28_Ch5 "CRCW04020000Z0ED" 0402 8585.7,5133.73 r90 top value=0 (schematic designator R28)
R28_Ch6 "CRCW04020000Z0ED" 0402 10147.7,5133.65 r90 top value=0 (schematic designator R28)
R28_Ch7 "CRCW04020000Z0ED" 0402 11709.7,5133.57 r90 top value=0 (schematic designator R28)
R28_Ch8 "CRCW04020000Z0ED" 0402 13271.7,5133.5 r90 top value=0 (schematic designator R28)
R29_Ch1 "CRCW04020000Z0ED" 0402 1998,5134.05 r90 top value=0 (schematic designator R29)
R29_Ch2 "CRCW04020000Z0ED" 0402 3560,5133.97 r90 top value=0 (schematic designator R29)
R29_Ch3 "CRCW04020000Z0ED" 0402 5122,5133.89 r90 top value=0 (schematic designator R29)
R29_Ch4 "CRCW04020000Z0ED" 0402 6684,5133.81 r90 top value=0 (schematic designator R29)
R29_Ch5 "CRCW04020000Z0ED" 0402 8639.7,5133.73 r90 top value=0 (schematic designator R29)
R29_Ch6 "CRCW04020000Z0ED" 0402 10201.7,5133.65 r90 top value=0 (schematic designator R29)
R29_Ch7 "CRCW04020000Z0ED" 0402 11763.7,5133.57 r90 top value=0 (schematic designator R29)
R29_Ch8 "CRCW04020000Z0ED" 0402 13325.7,5133.5 r90 top value=0 (schematic designator R29)
R30_Ch1 "RT0603BRD072K15L" 0603 1826,5368.05 r270 top value=2.15k (schematic designator R30)
R30_Ch2 "RT0603BRD072K15L" 0603 3388,5367.97 r270 top value=2.15k (schematic designator R30)
R30_Ch3 "RT0603BRD072K15L" 0603 4950,5367.89 r270 top value=2.15k (schematic designator R30)
R30_Ch4 "RT0603BRD072K15L" 0603 6512,5367.81 r270 top value=2.15k (schematic designator R30)
R30_Ch5 "RT0603BRD072K15L" 0603 8467.7,5367.73 r270 top value=2.15k (schematic designator R30)
R30_Ch6 "RT0603BRD072K15L" 0603 10029.7,5367.65 r270 top value=2.15k (schematic designator R30)
R30_Ch7 "RT0603BRD072K15L" 0603 11591.7,5367.57 r270 top value=2.15k (schematic designator R30)
R30_Ch8 "RT0603BRD072K15L" 0603 13153.7,5367.5 r270 top value=2.15k (schematic designator R30)
R31_Ch1 "CRCW04020000Z0ED" 0402 1973,5562.05 r0 top value=0 (schematic designator R31)
R31_Ch2 "CRCW04020000Z0ED" 0402 3535,5561.97 r0 top value=0 (schematic designator R31)
R31_Ch3 "CRCW04020000Z0ED" 0402 5097,5561.89 r0 top value=0 (schematic designator R31)
R31_Ch4 "CRCW04020000Z0ED" 0402 6659,5561.81 r0 top value=0 (schematic designator R31)
R31_Ch5 "CRCW04020000Z0ED" 0402 8614.7,5561.73 r0 top value=0 (schematic designator R31)
R31_Ch6 "CRCW04020000Z0ED" 0402 10176.7,5561.65 r0 top value=0 (schematic designator R31)
R31_Ch7 "CRCW04020000Z0ED" 0402 11738.7,5561.57 r0 top value=0 (schematic designator R31)
R31_Ch8 "CRCW04020000Z0ED" 0402 13300.7,5561.5 r0 top value=0 (schematic designator R31)
R32_Ch1 "CRCW04020000Z0ED" 0402 2058,5585.05 r90 top value=0 (schematic designator R32)
R32_Ch2 "CRCW04020000Z0ED" 0402 3620,5584.97 r90 top value=0 (schematic designator R32)
R32_Ch3 "CRCW04020000Z0ED" 0402 5182,5584.89 r90 top value=0 (schematic designator R32)
R32_Ch4 "CRCW04020000Z0ED" 0402 6744,5584.81 r90 top value=0 (schematic designator R32)
R32_Ch5 "CRCW04020000Z0ED" 0402 8699.7,5584.73 r90 top value=0 (schematic designator R32)
R32_Ch6 "CRCW04020000Z0ED" 0402 10261.7,5584.65 r90 top value=0 (schematic designator R32)
R32_Ch7 "CRCW04020000Z0ED" 0402 11823.7,5584.57 r90 top value=0 (schematic designator R32)
R32_Ch8 "CRCW04020000Z0ED" 0402 13385.7,5584.5 r90 top value=0 (schematic designator R32)
R33_Ch1 "PNM0402E5000BST1" 0402 2057,5694.05 r90 top value=500 (schematic designator R33)
R33_Ch2 "PNM0402E5000BST1" 0402 3619,5693.97 r90 top value=500 (schematic designator R33)
R33_Ch3 "PNM0402E5000BST1" 0402 5181,5693.89 r90 top value=500 (schematic designator R33)
R33_Ch4 "PNM0402E5000BST1" 0402 6743,5693.81 r90 top value=500 (schematic designator R33)
R33_Ch5 "PNM0402E5000BST1" 0402 8698.7,5693.73 r90 top value=500 (schematic designator R33)
R33_Ch6 "PNM0402E5000BST1" 0402 10260.7,5693.65 r90 top value=500 (schematic designator R33)
R33_Ch7 "PNM0402E5000BST1" 0402 11822.7,5693.57 r90 top value=500 (schematic designator R33)
R33_Ch8 "PNM0402E5000BST1" 0402 13384.7,5693.5 r90 top value=500 (schematic designator R33)
R34_Ch1 "PNM0402E5000BST1" 0402 2057,5868.05 r90 top value=500 (schematic designator R34)
R34_Ch2 "PNM0402E5000BST1" 0402 3619,5867.97 r90 top value=500 (schematic designator R34)
R34_Ch3 "PNM0402E5000BST1" 0402 5181,5867.89 r90 top value=500 (schematic designator R34)
R34_Ch4 "PNM0402E5000BST1" 0402 6743,5867.81 r90 top value=500 (schematic designator R34)
R34_Ch5 "PNM0402E5000BST1" 0402 8698.7,5867.73 r90 top value=500 (schematic designator R34)
R34_Ch6 "PNM0402E5000BST1" 0402 10260.7,5867.65 r90 top value=500 (schematic designator R34)
R34_Ch7 "PNM0402E5000BST1" 0402 11822.7,5867.57 r90 top value=500 (schematic designator R34)
R34_Ch8 "PNM0402E5000BST1" 0402 13384.7,5867.5 r90 top value=500 (schematic designator R34)
R35_Ch1 "PNM0402E5000BST1" 0402 2057,6040.05 r90 top value=500 (schematic designator R35)
R35_Ch2 "PNM0402E5000BST1" 0402 3619,6039.97 r90 top value=500 (schematic designator R35)
R35_Ch3 "PNM0402E5000BST1" 0402 5181,6039.89 r90 top value=500 (schematic designator R35)
R35_Ch4 "PNM0402E5000BST1" 0402 6743,6039.81 r90 top value=500 (schematic designator R35)
R35_Ch5 "PNM0402E5000BST1" 0402 8698.7,6039.73 r90 top value=500 (schematic designator R35)
R35_Ch6 "PNM0402E5000BST1" 0402 10260.7,6039.65 r90 top value=500 (schematic designator R35)
R35_Ch7 "PNM0402E5000BST1" 0402 11822.7,6039.57 r90 top value=500 (schematic designator R35)
R35_Ch8 "PNM0402E5000BST1" 0402 13384.7,6039.5 r90 top value=500 (schematic designator R35)
R36_Ch1 "PNM0402E5000BST1" 0402 3655.87,7404.63 r0 top value=500 (schematic designator R36)
R36_Ch2 "PNM0402E5000BST1" 0402 3961.75,6560.05 r90 top value=500 (schematic designator R36)
R36_Ch3 "PNM0402E5000BST1" 0402 4481.61,6560.05 r90 top value=500 (schematic designator R36)
R36_Ch4 "PNM0402E5000BST1" 0402 5097.42,7085.03 r180 top value=500 (schematic designator R36)
R36_Ch5 "PNM0402E5000BST1" 0402 10297.58,7404.32 r0 top value=500 (schematic designator R36)
R36_Ch6 "PNM0402E5000BST1" 0402 10603.45,6559.73 r90 top value=500 (schematic designator R36)
R36_Ch7 "PNM0402E5000BST1" 0402 11123.31,6559.73 r90 top value=500 (schematic designator R36)
R36_Ch8 "PNM0402E5000BST1" 0402 11739.12,7084.71 r180 top value=500 (schematic designator R36)
R37_Ch1 "PNM0402E5000BST1" 0402 2106,5694.05 r90 top value=500 (schematic designator R37)
R37_Ch2 "PNM0402E5000BST1" 0402 3668,5693.97 r90 top value=500 (schematic designator R37)
R37_Ch3 "PNM0402E5000BST1" 0402 5230,5693.89 r90 top value=500 (schematic designator R37)
R37_Ch4 "PNM0402E5000BST1" 0402 6792,5693.81 r90 top value=500 (schematic designator R37)
R37_Ch5 "PNM0402E5000BST1" 0402 8747.7,5693.73 r90 top value=500 (schematic designator R37)
R37_Ch6 "PNM0402E5000BST1" 0402 10309.7,5693.65 r90 top value=500 (schematic designator R37)
R37_Ch7 "PNM0402E5000BST1" 0402 11871.7,5693.57 r90 top value=500 (schematic designator R37)
R37_Ch8 "PNM0402E5000BST1" 0402 13433.7,5693.5 r90 top value=500 (schematic designator R37)
R38_Ch1 "PNM0402E5000BST1" 0402 2106,5868.05 r90 top value=500 (schematic designator R38)
R38_Ch2 "PNM0402E5000BST1" 0402 3668,5867.97 r90 top value=500 (schematic designator R38)
R38_Ch3 "PNM0402E5000BST1" 0402 5230,5867.89 r90 top value=500 (schematic designator R38)
R38_Ch4 "PNM0402E5000BST1" 0402 6792,5867.81 r90 top value=500 (schematic designator R38)
R38_Ch5 "PNM0402E5000BST1" 0402 8747.7,5867.73 r90 top value=500 (schematic designator R38)
R38_Ch6 "PNM0402E5000BST1" 0402 10309.7,5867.65 r90 top value=500 (schematic designator R38)
R38_Ch7 "PNM0402E5000BST1" 0402 11871.7,5867.57 r90 top value=500 (schematic designator R38)
R38_Ch8 "PNM0402E5000BST1" 0402 13433.7,5867.5 r90 top value=500 (schematic designator R38)
R39_Ch1 "PNM0402E5000BST1" 0402 2106,6040.05 r90 top value=500 (schematic designator R39)
R39_Ch2 "PNM0402E5000BST1" 0402 3668,6039.97 r90 top value=500 (schematic designator R39)
R39_Ch3 "PNM0402E5000BST1" 0402 5230,6039.89 r90 top value=500 (schematic designator R39)
R39_Ch4 "PNM0402E5000BST1" 0402 6792,6039.81 r90 top value=500 (schematic designator R39)
R39_Ch5 "PNM0402E5000BST1" 0402 8747.7,6039.73 r90 top value=500 (schematic designator R39)
R39_Ch6 "PNM0402E5000BST1" 0402 10309.7,6039.65 r90 top value=500 (schematic designator R39)
R39_Ch7 "PNM0402E5000BST1" 0402 11871.7,6039.57 r90 top value=500 (schematic designator R39)
R39_Ch8 "PNM0402E5000BST1" 0402 13433.7,6039.5 r90 top value=500 (schematic designator R39)
R40_Ch1 "PNM0402E5000BST1" 0402 3655.87,7355.63 r0 top value=500 (schematic designator R40)
R40_Ch2 "PNM0402E5000BST1" 0402 4010.75,6560.05 r90 top value=500 (schematic designator R40)
R40_Ch3 "PNM0402E5000BST1" 0402 4530.61,6560.05 r90 top value=500 (schematic designator R40)
R40_Ch4 "PNM0402E5000BST1" 0402 5097.42,7134.03 r180 top value=500 (schematic designator R40)
R40_Ch5 "PNM0402E5000BST1" 0402 10297.58,7355.32 r0 top value=500 (schematic designator R40)
R40_Ch6 "PNM0402E5000BST1" 0402 10652.45,6559.73 r90 top value=500 (schematic designator R40)
R40_Ch7 "PNM0402E5000BST1" 0402 11172.31,6559.73 r90 top value=500 (schematic designator R40)
R40_Ch8 "PNM0402E5000BST1" 0402 11739.12,7133.71 r180 top value=500 (schematic designator R40)
R41_Ch1 "CRCW04020000Z0ED" 0402 2275,5588.05 r270 top value=0 (schematic designator R41)
R41_Ch2 "CRCW04020000Z0ED" 0402 3837,5587.97 r270 top value=0 (schematic designator R41)
R41_Ch3 "CRCW04020000Z0ED" 0402 5399,5587.89 r270 top value=0 (schematic designator R41)
R41_Ch4 "CRCW04020000Z0ED" 0402 6961,5587.81 r270 top value=0 (schematic designator R41)
R41_Ch5 "CRCW04020000Z0ED" 0402 8916.7,5587.73 r270 top value=0 (schematic designator R41)
R41_Ch6 "CRCW04020000Z0ED" 0402 10478.7,5587.65 r270 top value=0 (schematic designator R41)
R41_Ch7 "CRCW04020000Z0ED" 0402 12040.7,5587.57 r270 top value=0 (schematic designator R41)
R41_Ch8 "CRCW04020000Z0ED" 0402 13602.7,5587.5 r270 top value=0 (schematic designator R41)
R42 "CRCW040210K0FKED" 0402 7335,6792.01 r0 top value=10.0k
R43_Ch1 "CRCW04020000Z0ED" 0402 1996.62,5538.43 r270 bottom value=0 (schematic designator R43)
R43_Ch2 "CRCW04020000Z0ED" 0402 3558.62,5538.35 r270 bottom value=0 (schematic designator R43)
R43_Ch3 "CRCW04020000Z0ED" 0402 5120.62,5538.27 r270 bottom value=0 (schematic designator R43)
R43_Ch4 "CRCW04020000Z0ED" 0402 6682.62,5538.19 r270 bottom value=0 (schematic designator R43)
R43_Ch5 "CRCW04020000Z0ED" 0402 8638.32,5538.11 r270 bottom value=0 (schematic designator R43)
R43_Ch6 "CRCW04020000Z0ED" 0402 10200.32,5538.03 r270 bottom value=0 (schematic designator R43)
R43_Ch7 "CRCW04020000Z0ED" 0402 11762.32,5537.95 r270 bottom value=0 (schematic designator R43)
R43_Ch8 "CRCW04020000Z0ED" 0402 13324.32,5537.87 r270 bottom value=0 (schematic designator R43)
R44_Ch1 "RT0603BRD072KL" 0603 2207,5480.05 r270 bottom value=2.00k (schematic designator R44)
R44_Ch2 "RT0603BRD072KL" 0603 3769,5479.97 r270 bottom value=2.00k (schematic designator R44)
R44_Ch3 "RT0603BRD072KL" 0603 5331,5479.89 r270 bottom value=2.00k (schematic designator R44)
R44_Ch4 "RT0603BRD072KL" 0603 6893,5479.81 r270 bottom value=2.00k (schematic designator R44)
R44_Ch5 "RT0603BRD072KL" 0603 8848.7,5479.73 r270 bottom value=2.00k (schematic designator R44)
R44_Ch6 "RT0603BRD072KL" 0603 10410.7,5479.65 r270 bottom value=2.00k (schematic designator R44)
R44_Ch7 "RT0603BRD072KL" 0603 11972.7,5479.57 r270 bottom value=2.00k (schematic designator R44)
R44_Ch8 "RT0603BRD072KL" 0603 13534.7,5479.5 r270 bottom value=2.00k (schematic designator R44)
R45_Ch1 "CRCW04020000Z0ED" 0402 2390,5364.05 r90 bottom value=0 (schematic designator R45)
R45_Ch2 "CRCW04020000Z0ED" 0402 3952,5363.97 r90 bottom value=0 (schematic designator R45)
R45_Ch3 "CRCW04020000Z0ED" 0402 5514,5363.89 r90 bottom value=0 (schematic designator R45)
R45_Ch4 "CRCW04020000Z0ED" 0402 7076,5363.81 r90 bottom value=0 (schematic designator R45)
R45_Ch5 "CRCW04020000Z0ED" 0402 9031.7,5363.73 r90 bottom value=0 (schematic designator R45)
R45_Ch6 "CRCW04020000Z0ED" 0402 10593.7,5363.65 r90 bottom value=0 (schematic designator R45)
R45_Ch7 "CRCW04020000Z0ED" 0402 12155.7,5363.57 r90 bottom value=0 (schematic designator R45)
R45_Ch8 "CRCW04020000Z0ED" 0402 13717.7,5363.5 r90 bottom value=0 (schematic designator R45)
R46_Ch1 "RT0603BRD077K96L" 0603 2142,5480.05 r270 bottom value=7.96k (schematic designator R46)
R46_Ch2 "RT0603BRD077K96L" 0603 3704,5479.97 r270 bottom value=7.96k (schematic designator R46)
R46_Ch3 "RT0603BRD077K96L" 0603 5266,5479.89 r270 bottom value=7.96k (schematic designator R46)
R46_Ch4 "RT0603BRD077K96L" 0603 6828,5479.81 r270 bottom value=7.96k (schematic designator R46)
R46_Ch5 "RT0603BRD077K96L" 0603 8783.7,5479.73 r270 bottom value=7.96k (schematic designator R46)
R46_Ch6 "RT0603BRD077K96L" 0603 10345.7,5479.65 r270 bottom value=7.96k (schematic designator R46)
R46_Ch7 "RT0603BRD077K96L" 0603 11907.7,5479.57 r270 bottom value=7.96k (schematic designator R46)
R46_Ch8 "RT0603BRD077K96L" 0603 13469.7,5479.5 r270 bottom value=7.96k (schematic designator R46)
R47_Ch1 "CRCW04020000Z0ED" 0402 2341,5364.05 r90 bottom value=0 (schematic designator R47)
R47_Ch2 "CRCW04020000Z0ED" 0402 3903,5363.97 r90 bottom value=0 (schematic designator R47)
R47_Ch3 "CRCW04020000Z0ED" 0402 5465,5363.89 r90 bottom value=0 (schematic designator R47)
R47_Ch4 "CRCW04020000Z0ED" 0402 7027,5363.81 r90 bottom value=0 (schematic designator R47)
R47_Ch5 "CRCW04020000Z0ED" 0402 8982.7,5363.73 r90 bottom value=0 (schematic designator R47)
R47_Ch6 "CRCW04020000Z0ED" 0402 10544.7,5363.65 r90 bottom value=0 (schematic designator R47)
R47_Ch7 "CRCW04020000Z0ED" 0402 12106.7,5363.57 r90 bottom value=0 (schematic designator R47)
R47_Ch8 "CRCW04020000Z0ED" 0402 13668.7,5363.5 r90 bottom value=0 (schematic designator R47)
R48_Ch1 "CRCW04020000Z0ED" 0402 2021,5656.05 r0 bottom value=0 (schematic designator R48)
R48_Ch2 "CRCW04020000Z0ED" 0402 3583,5655.97 r0 bottom value=0 (schematic designator R48)
R48_Ch3 "CRCW04020000Z0ED" 0402 5145,5655.89 r0 bottom value=0 (schematic designator R48)
R48_Ch4 "CRCW04020000Z0ED" 0402 6707,5655.81 r0 bottom value=0 (schematic designator R48)
R48_Ch5 "CRCW04020000Z0ED" 0402 8662.7,5655.73 r0 bottom value=0 (schematic designator R48)
R48_Ch6 "CRCW04020000Z0ED" 0402 10224.7,5655.65 r0 bottom value=0 (schematic designator R48)
R48_Ch7 "CRCW04020000Z0ED" 0402 11786.7,5655.57 r0 bottom value=0 (schematic designator R48)
R48_Ch8 "CRCW04020000Z0ED" 0402 13348.7,5655.5 r0 bottom value=0 (schematic designator R48)
R49_Ch1 "CRCW04020000Z0ED" 0402 2275,5588.05 r270 bottom value=0 (schematic designator R49)
R49_Ch2 "CRCW04020000Z0ED" 0402 3837,5587.97 r270 bottom value=0 (schematic designator R49)
R49_Ch3 "CRCW04020000Z0ED" 0402 5399,5587.89 r270 bottom value=0 (schematic designator R49)
R49_Ch4 "CRCW04020000Z0ED" 0402 6961,5587.81 r270 bottom value=0 (schematic designator R49)
R49_Ch5 "CRCW04020000Z0ED" 0402 8916.7,5587.73 r270 bottom value=0 (schematic designator R49)
R49_Ch6 "CRCW04020000Z0ED" 0402 10478.7,5587.65 r270 bottom value=0 (schematic designator R49)
R49_Ch7 "CRCW04020000Z0ED" 0402 12040.7,5587.57 r270 bottom value=0 (schematic designator R49)
R49_Ch8 "CRCW04020000Z0ED" 0402 13602.7,5587.5 r270 bottom value=0 (schematic designator R49)
R50_Ch1 "CRCW04022K70JNED" 0402 2274,5872.05 r90 bottom value=2.7k (schematic designator R50)
R50_Ch2 "CRCW04022K70JNED" 0402 3836,5871.97 r90 bottom value=2.7k (schematic designator R50)
R50_Ch3 "CRCW04022K70JNED" 0402 5398,5871.89 r90 bottom value=2.7k (schematic designator R50)
R50_Ch4 "CRCW04022K70JNED" 0402 6960,5871.81 r90 bottom value=2.7k (schematic designator R50)
R50_Ch5 "CRCW04022K70JNED" 0402 8915.7,5871.73 r90 bottom value=2.7k (schematic designator R50)
R50_Ch6 "CRCW04022K70JNED" 0402 10477.7,5871.65 r90 bottom value=2.7k (schematic designator R50)
R50_Ch7 "CRCW04022K70JNED" 0402 12039.7,5871.57 r90 bottom value=2.7k (schematic designator R50)
R50_Ch8 "CRCW04022K70JNED" 0402 13601.7,5871.5 r90 bottom value=2.7k (schematic designator R50)
R51_Ch1 "CRCW04025K10JNED" 0402 1995,5976.67 r90 bottom value=5.1k (schematic designator R51)
R51_Ch2 "CRCW04025K10JNED" 0402 3557,5976.59 r90 bottom value=5.1k (schematic designator R51)
R51_Ch3 "CRCW04025K10JNED" 0402 5119,5976.51 r90 bottom value=5.1k (schematic designator R51)
R51_Ch4 "CRCW04025K10JNED" 0402 6681,5976.43 r90 bottom value=5.1k (schematic designator R51)
R51_Ch5 "CRCW04025K10JNED" 0402 8636.7,5976.35 r90 bottom value=5.1k (schematic designator R51)
R51_Ch6 "CRCW04025K10JNED" 0402 10198.7,5976.28 r90 bottom value=5.1k (schematic designator R51)
R51_Ch7 "CRCW04025K10JNED" 0402 11760.7,5976.2 r90 bottom value=5.1k (schematic designator R51)
R51_Ch8 "CRCW04025K10JNED" 0402 13322.7,5976.12 r90 bottom value=5.1k (schematic designator R51)
R52_Ch1 "CRCW04027K50FKED" 0402 2132,5656.05 r0 bottom value=7.50k (schematic designator R52)
R52_Ch2 "CRCW04027K50FKED" 0402 3694,5655.97 r0 bottom value=7.50k (schematic designator R52)
R52_Ch3 "CRCW04027K50FKED" 0402 5256,5655.89 r0 bottom value=7.50k (schematic designator R52)
R52_Ch4 "CRCW04027K50FKED" 0402 6818,5655.81 r0 bottom value=7.50k (schematic designator R52)
R52_Ch5 "CRCW04027K50FKED" 0402 8773.7,5655.73 r0 bottom value=7.50k (schematic designator R52)
R52_Ch6 "CRCW04027K50FKED" 0402 10335.7,5655.65 r0 bottom value=7.50k (schematic designator R52)
R52_Ch7 "CRCW04027K50FKED" 0402 11897.7,5655.57 r0 bottom value=7.50k (schematic designator R52)
R52_Ch8 "CRCW04027K50FKED" 0402 13459.7,5655.5 r0 bottom value=7.50k (schematic designator R52)
R53_Ch1 "CRCW040211K0FKED" 0402 2132,5706.05 r180 bottom value=11.0k (schematic designator R53)
R53_Ch2 "CRCW040211K0FKED" 0402 3694,5705.97 r180 bottom value=11.0k (schematic designator R53)
R53_Ch3 "CRCW040211K0FKED" 0402 5256,5705.89 r180 bottom value=11.0k (schematic designator R53)
R53_Ch4 "CRCW040211K0FKED" 0402 6818,5705.81 r180 bottom value=11.0k (schematic designator R53)
R53_Ch5 "CRCW040211K0FKED" 0402 8773.7,5705.73 r180 bottom value=11.0k (schematic designator R53)
R53_Ch6 "CRCW040211K0FKED" 0402 10335.7,5705.65 r180 bottom value=11.0k (schematic designator R53)
R53_Ch7 "CRCW040211K0FKED" 0402 11897.7,5705.57 r180 bottom value=11.0k (schematic designator R53)
R53_Ch8 "CRCW040211K0FKED" 0402 13459.7,5705.5 r180 bottom value=11.0k (schematic designator R53)
R54 "CRCW04020000Z0ED" 0402 7558,6971.01 r0 top value=0
R55 "CRCW04020000Z0ED" 0402 7558,6921.01 r0 top value=0
R56 "CRCW04020000Z0ED" 0402 7558,6871.01 r0 top value=0
R57 "CRCW04020000Z0ED" 0402 7558,6821.01 r0 top value=0
R58 "CRCW04020000Z0ED" 0402 7161,7879.7 r270 top value=0
R59 "CRCW06034K99FKEA" 0603L 7105,7880 r90 top value=4.99k
R61_Ch1 "CRCW040210K0FKED" 0402 1814,5873.7 r180 bottom value=10.0k (schematic designator R61)
R61_Ch2 "CRCW040210K0FKED" 0402 3376,5873.62 r180 bottom value=10.0k (schematic designator R61)
R61_Ch3 "CRCW040210K0FKED" 0402 4938,5873.54 r180 bottom value=10.0k (schematic designator R61)
R61_Ch4 "CRCW040210K0FKED" 0402 6500,5873.46 r180 bottom value=10.0k (schematic designator R61)
R61_Ch5 "CRCW040210K0FKED" 0402 8455.7,5873.39 r180 bottom value=10.0k (schematic designator R61)
R61_Ch6 "CRCW040210K0FKED" 0402 10017.7,5873.31 r180 bottom value=10.0k (schematic designator R61)
R61_Ch7 "CRCW040210K0FKED" 0402 11579.7,5873.23 r180 bottom value=10.0k (schematic designator R61)
R61_Ch8 "CRCW040210K0FKED" 0402 13141.7,5873.15 r180 bottom value=10.0k (schematic designator R61)
R62_Ch1 "CRCW040210K0FKED" 0402 1814,5824.7 r0 bottom value=10.0k (schematic designator R62)
R62_Ch2 "CRCW040210K0FKED" 0402 3376,5824.62 r0 bottom value=10.0k (schematic designator R62)
R62_Ch3 "CRCW040210K0FKED" 0402 4938,5824.54 r0 bottom value=10.0k (schematic designator R62)
R62_Ch4 "CRCW040210K0FKED" 0402 6500,5824.46 r0 bottom value=10.0k (schematic designator R62)
R62_Ch5 "CRCW040210K0FKED" 0402 8455.7,5824.39 r0 bottom value=10.0k (schematic designator R62)
R62_Ch6 "CRCW040210K0FKED" 0402 10017.7,5824.31 r0 bottom value=10.0k (schematic designator R62)
R62_Ch7 "CRCW040210K0FKED" 0402 11579.7,5824.23 r0 bottom value=10.0k (schematic designator R62)
R62_Ch8 "CRCW040210K0FKED" 0402 13141.7,5824.15 r0 bottom value=10.0k (schematic designator R62)
R63_Ch1 "RT0603BRD0724KL" 0603 2627.54,5332.68 r180 top value=24.0k (schematic designator R63)
R63_Ch2 "RT0603BRD0724KL" 0603 4189.54,5332.6 r180 top value=24.0k (schematic designator R63)
R63_Ch3 "RT0603BRD0724KL" 0603 5751.54,5332.52 r180 top value=24.0k (schematic designator R63)
R63_Ch4 "RT0603BRD0724KL" 0603 7313.54,5332.44 r180 top value=24.0k (schematic designator R63)
R63_Ch5 "RT0603BRD0724KL" 0603 9269.24,5332.36 r180 top value=24.0k (schematic designator R63)
R63_Ch6 "RT0603BRD0724KL" 0603 10831.24,5332.28 r180 top value=24.0k (schematic designator R63)
R63_Ch7 "RT0603BRD0724KL" 0603 12393.24,5332.2 r180 top value=24.0k (schematic designator R63)
R63_Ch8 "RT0603BRD0724KL" 0603 13955.24,5332.13 r180 top value=24.0k (schematic designator R63)
R64_Ch1 "RT0603BRD07100KL" 0603 2627.54,5268.3 r0 top value=100k (schematic designator R64)
R64_Ch2 "RT0603BRD07100KL" 0603 4189.54,5268.22 r0 top value=100k (schematic designator R64)
R64_Ch3 "RT0603BRD07100KL" 0603 5751.54,5268.14 r0 top value=100k (schematic designator R64)
R64_Ch4 "RT0603BRD07100KL" 0603 7313.54,5268.06 r0 top value=100k (schematic designator R64)
R64_Ch5 "RT0603BRD07100KL" 0603 9269.24,5267.98 r0 top value=100k (schematic designator R64)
